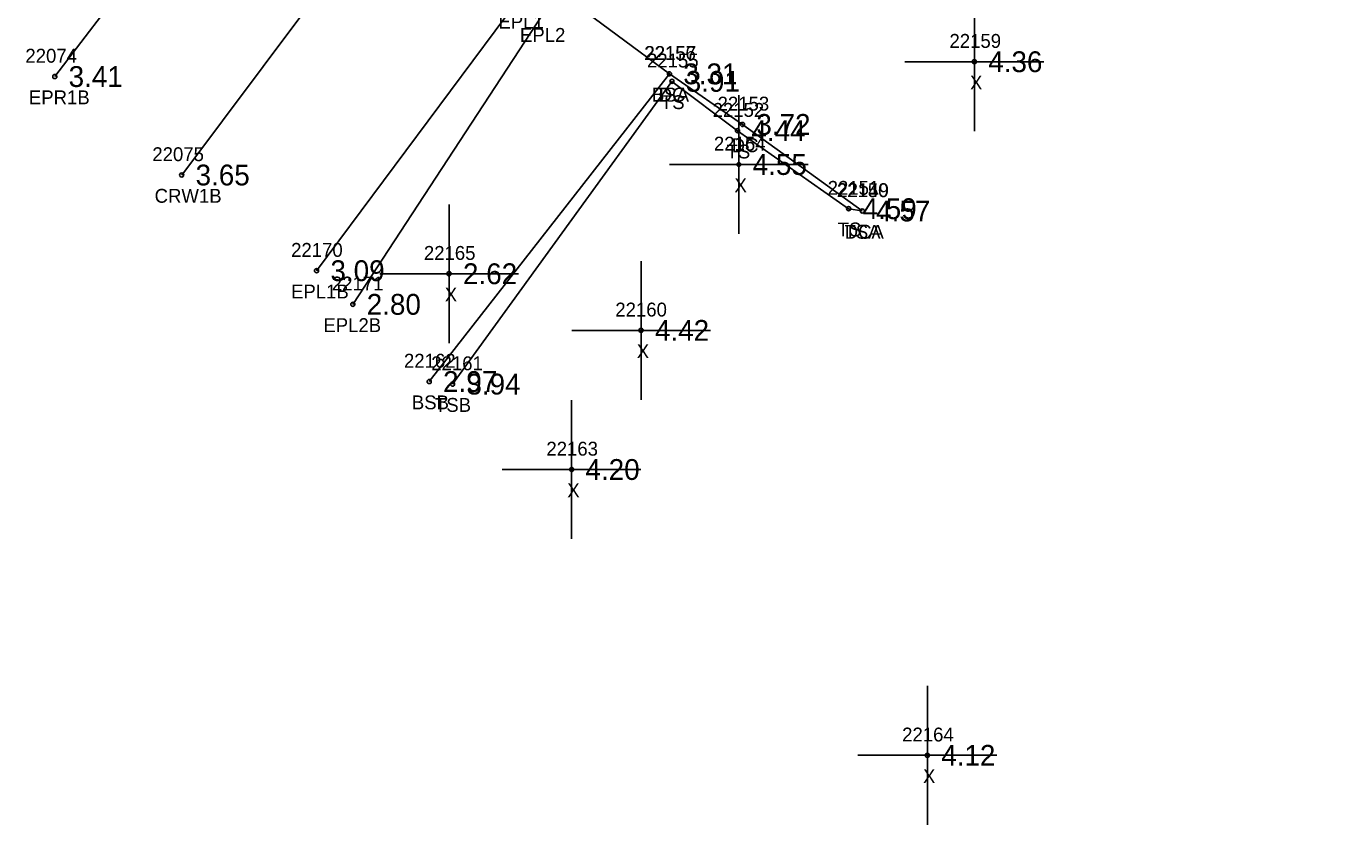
# Model space of a CAD drawing. Extents: x 2608745 to 2610333, y 641917 to 643463.
# Drawn here: x 2609963.9 to 2610058.8, y 641920.7 to 641978.2 of the extents above; entities that cross this region are included whole.
import ezdxf

# ---------------------------------------------------------------- set-up
doc = ezdxf.new("R2010")
doc.units = 0
for name, color, linetype in [('RD_DTM_BkLn1', 7, 'Continuous'), ('RD_DTM_BkLn2', 7, 'Continuous'), ('RD_DTM_BkLn_txCode', 7, 'Continuous'), ('RD_EX_Conc', 7, 'Continuous'), ('RD_EX_Conc_txCode', 7, 'Continuous'), ('RD_EX_Misc', 7, 'Continuous'), ('RD_EX_Misc_txCode', 7, 'Continuous'), ('RD_EX_Road', 7, 'Continuous'), ('RD_EX_Road_txCode', 7, 'Continuous'), ('RD_EX_TX_Conc_ELEV', 7, 'Continuous'), ('RD_EX_TX_Misc_ELEV', 7, 'Continuous'), ('RD_EX_TX_Road_ELEV', 7, 'Continuous'), ('RD_HC_Survey_ELEV', 7, 'Continuous'), ('RD_HC_Survey_txCode', 7, 'Continuous'), ('RD_SMD_Locator', 7, 'Continuous')]:
    doc.layers.add(name, color=color, linetype=linetype)

msp = doc.modelspace()

# ---------------------------------------------------------------- linework, layer by layer
at = {"layer": 'RD_DTM_BkLn1'}
msp.add_lwpolyline([(2610092.08, 642124.262), (2610033.919, 642046.064), (2609975.15, 641967.52)], dxfattribs=at)
at = {"layer": 'RD_DTM_BkLn2'}
msp.add_line((2610010.305, 641974.813), (2609992.989, 641952.632), dxfattribs=at)
msp.add_lwpolyline([(2610024.204, 641964.927), (2610023.222, 641965.093), (2610015.212, 641970.714), (2610010.483, 641974.272), (2609994.67, 641952.447)], dxfattribs=at)
at = {"layer": 'RD_EX_Conc'}
msp.add_lwpolyline([(2610024.204, 641964.927), (2610015.571, 641971.166), (2610010.305, 641974.813), (2610002.773, 641980.423)], dxfattribs=at)
at = {"layer": 'RD_EX_Misc'}
for p, q in [((2610032.283, 641970.687), (2610032.283, 641980.687)), ((2610027.283, 641975.687), (2610037.283, 641975.687)), ((2610015.306, 641963.278), (2610015.306, 641973.278)), ((2610010.306, 641968.278), (2610020.306, 641968.278)), ((2609994.424, 641955.403), (2609994.424, 641965.403)), ((2610008.262, 641951.321), (2610008.262, 641961.321)), ((2609989.424, 641960.403), (2609999.424, 641960.403)), ((2610003.262, 641956.321), (2610013.262, 641956.321)), ((2610003.254, 641941.291), (2610003.254, 641951.291)), ((2609998.254, 641946.291), (2610008.254, 641946.291)), ((2610028.895, 641920.688), (2610028.895, 641930.688)), ((2610023.895, 641925.688), (2610033.895, 641925.688))]:
    msp.add_line(p, q, dxfattribs=at)
at = {"layer": 'RD_EX_Road'}
for points in [[(2610073.957, 642143.053), (2610073.967, 642133.893), (2610072.62, 642129.267), (2610072.125, 642123.733), (2610071.192, 642117.593), (2610042.94, 642077.419), (2610042.982, 642077.082), (2610020.807, 642047.622), (2610010.682, 642034.572), (2609995.36, 642013.506), (2609993.975, 642012.164), (2609992.649, 642010.593), (2609982.727, 641996.329), (2609971.725, 641982.02), (2609971.56, 641981.898), (2609965.999, 641974.618)], [(2610116.512, 642103.007), (2610109.419, 642106.335), (2610102.937, 642107.104), (2610095.974, 642105.732), (2610091.028, 642103.088), (2610067.446, 642071.713), (2610058.11, 642059.075), (2610043.044, 642039.371), (2610035.942, 642029.795), (2610030.832, 642022.851), (2609999.348, 641980.077), (2609984.87, 641960.622)], [(2610032.589, 642022.148), (2610025.693, 642013.504), (2610020.985, 642006.523), (2610018.112, 642001.928), (2610002.773, 641980.423), (2610001.184, 641979.118), (2609987.485, 641958.197)]]:
    msp.add_lwpolyline(points, dxfattribs=at)
at = {"layer": 'RD_SMD_Locator'}
for centre in [(2610032.283, 641975.687), (2609965.999, 641974.618), (2610010.305, 641974.813), (2610010.305, 641974.813), (2610010.483, 641974.272), (2610015.212, 641970.714), (2610015.571, 641971.166), (2610015.306, 641968.278), (2609975.15, 641967.52), (2610023.222, 641965.093), (2610024.204, 641964.927), (2610024.204, 641964.927), (2609984.87, 641960.622), (2609994.424, 641960.403), (2609987.485, 641958.197), (2610008.262, 641956.321), (2609992.989, 641952.632), (2609994.67, 641952.447), (2610003.254, 641946.291), (2610028.895, 641925.688)]:
    msp.add_circle(centre, 0.15, dxfattribs=at)

# ---------------------------------------------------------------- texts
at = {"layer": 'RD_DTM_BkLn_txCode'}
for s, p in [('22157', (2610008.51, 641975.813)), ('22155', (2610008.688, 641975.272)), ('BSA', (2610009.037, 641972.813)), ('TS', (2610009.688, 641972.272)), ('22152', (2610013.417, 641971.714)), ('TS', (2610014.417, 641968.714)), ('22151', (2610021.71, 641966.093)), ('22150', (2610022.369, 641965.927)), ('TS', (2610022.426, 641963.093)), ('TSA', (2610022.92, 641962.927)), ('22162', (2609991.17, 641953.632)), ('22161', (2609993.135, 641953.447)), ('BSB', (2609991.737, 641950.632)), ('TSB', (2609993.403, 641950.447))]:
    msp.add_text(s, height=1, dxfattribs=at).set_placement(p)
at = {"layer": 'RD_EX_Conc_txCode'}
for s, p in [('22156', (2610008.486, 641975.813)), ('DC', (2610009.526, 641972.813)), ('22153', (2610013.776, 641972.166)), ('DC', (2610014.791, 641969.166)), ('22149', (2610022.408, 641965.927)), ('DCA', (2610022.936, 641962.927))]:
    msp.add_text(s, height=1, dxfattribs=at).set_placement(p)
at = {"layer": 'RD_EX_Misc_txCode'}
for s, p in [('22159', (2610030.488, 641976.687)), ('X', (2610031.968, 641973.687)), ('22154', (2610013.511, 641969.278)), ('X', (2610014.991, 641966.278)), ('22165', (2609992.605, 641961.403)), ('X', (2609994.109, 641958.403)), ('22160', (2610006.403, 641957.321)), ('X', (2610007.947, 641954.321)), ('22163', (2610001.435, 641947.291)), ('X', (2610002.939, 641944.291)), ('22164', (2610027.076, 641926.688)), ('X', (2610028.58, 641923.688))]:
    msp.add_text(s, height=1, dxfattribs=at).set_placement(p)
at = {"layer": 'RD_EX_Road_txCode'}
for s, p in [('EPL1', (2609997.978, 641978.077)), ('EPL2', (2609999.53, 641977.118)), ('22074', (2609963.881, 641975.618)), ('EPR1B', (2609964.133, 641972.618)), ('22170', (2609983.035, 641961.622)), ('EPL1B', (2609983.027, 641958.622)), ('22171', (2609985.973, 641959.197)), ('EPL2B', (2609985.359, 641956.197))]:
    msp.add_text(s, height=1, dxfattribs=at).set_placement(p)
at = {"layer": 'RD_EX_TX_Conc_ELEV'}
for s, p in [('3.31', (2610011.305, 641974.063)), ('3.72', (2610016.571, 641970.416)), ('4.57', (2610025.204, 641964.177))]:
    msp.add_text(s, height=1.5, dxfattribs=at).set_placement(p)
at = {"layer": 'RD_EX_TX_Misc_ELEV'}
for s, p in [('4.36', (2610033.283, 641974.937)), ('3.31', (2610011.305, 641974.063)), ('3.91', (2610011.483, 641973.522)), ('4.44', (2610016.212, 641969.964)), ('4.55', (2610016.306, 641967.528)), ('4.59', (2610024.222, 641964.343)), ('4.57', (2610025.204, 641964.177)), ('2.62', (2609995.424, 641959.653)), ('4.42', (2610009.262, 641955.571)), ('2.97', (2609993.989, 641951.882)), ('3.94', (2609995.67, 641951.697)), ('4.20', (2610004.254, 641945.541)), ('4.12', (2610029.895, 641924.938))]:
    msp.add_text(s, height=1.5, dxfattribs=at).set_placement(p)
at = {"layer": 'RD_EX_TX_Road_ELEV'}
for s, p in [('3.41', (2609966.999, 641973.868)), ('3.09', (2609985.87, 641959.872)), ('2.80', (2609988.485, 641957.447))]:
    msp.add_text(s, height=1.5, dxfattribs=at).set_placement(p)
at = {"layer": 'RD_HC_Survey_ELEV'}
msp.add_text('3.65', height=1.5, dxfattribs=at).set_placement((2609976.15, 641966.77))
at = {"layer": 'RD_HC_Survey_txCode'}
for s, p in [('22075', (2609973.032, 641968.52)), ('CRW1B', (2609973.197, 641965.52))]:
    msp.add_text(s, height=1, dxfattribs=at).set_placement(p)

doc.saveas('drawing.dxf')
